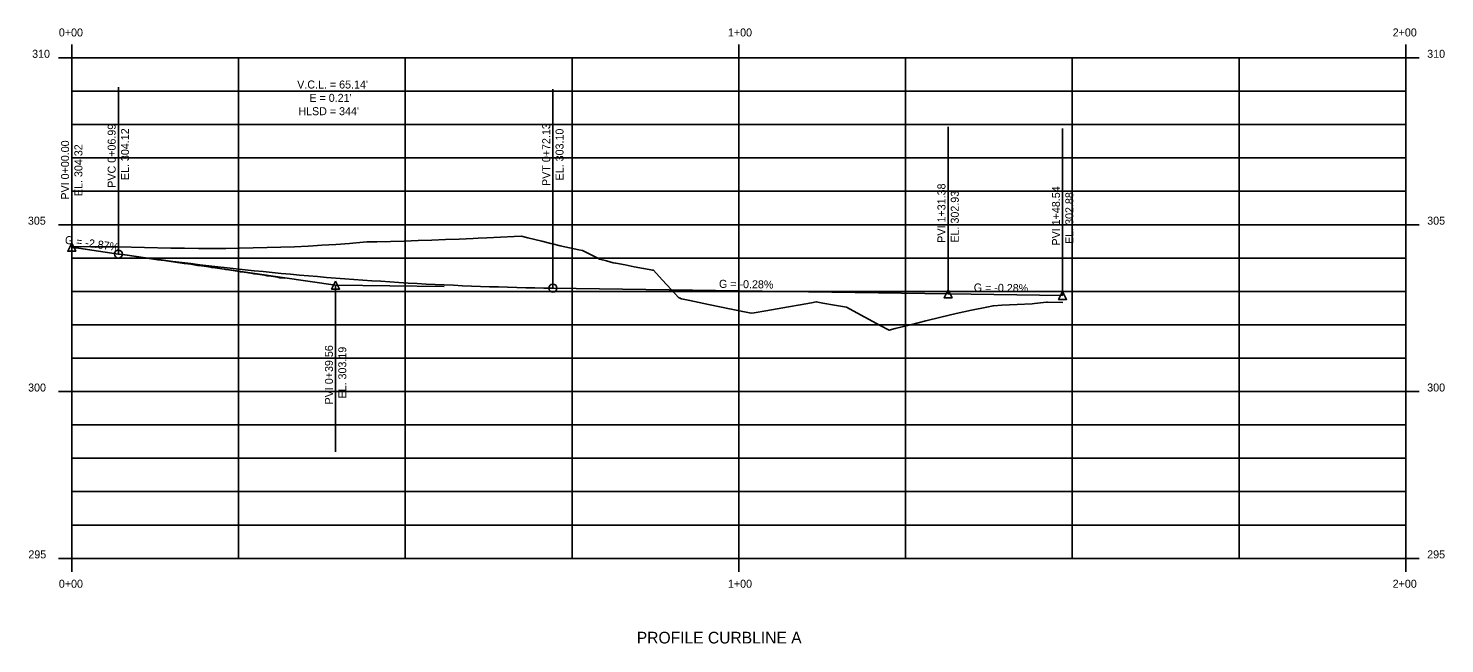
# Model space of a CAD drawing. Extents: x 916627 to 921213, y 329780 to 330157.
# Drawn here: x 919973.2 to 920185.5, y 329794.6 to 329886.8 of the extents above; entities that cross this region are included whole.
import ezdxf

# ---------------------------------------------------------------- set-up
doc = ezdxf.new("R2010")
doc.units = 0
for name, color, linetype in [('D_Roadway_Centerline', 7, 'Continuous'), ('D_Roadway_Centerline_Bearings', 7, 'Continuous'), ('D_Roadway_Centerline_CurveData', 7, 'Continuous'), ('D_Roadway_Centerline_Text', 7, 'Continuous'), ('D_Roadway_Edge_TW', 7, 'Continuous')]:
    doc.layers.add(name, color=color, linetype=linetype)

msp = doc.modelspace()

# ---------------------------------------------------------------- linework, layer by layer
at = {"layer": 'D_Roadway_Centerline'}
for p, q in [((919979.72, 329884.41), (919979.72, 329882.41)), ((920079.72, 329884.41), (920079.72, 329882.41)), ((920179.72, 329884.41), (920179.72, 329882.41)), ((919977.72, 329882.41), (919979.72, 329882.41)), ((919977.72, 329882.41), (919979.72, 329882.41)), ((919979.72, 329882.41), (920179.72, 329882.41)), ((919979.72, 329807.41), (919979.72, 329882.41)), ((920079.72, 329807.41), (920079.72, 329882.41)), ((920179.72, 329807.41), (920179.72, 329882.41)), ((920181.72, 329882.41), (920179.72, 329882.41)), ((920181.72, 329882.41), (920179.72, 329882.41)), ((919977.72, 329857.41), (919979.72, 329857.41)), ((919979.72, 329857.41), (920179.72, 329857.41)), ((920181.72, 329857.41), (920179.72, 329857.41)), ((919979.72, 329854.02), (919986.71, 329853.01)), ((920051.85, 329847.9), (920111.1, 329847.06)), ((920111.1, 329847.06), (920128.27, 329846.82)), ((919977.72, 329832.41), (919979.72, 329832.41)), ((919979.72, 329832.41), (920179.72, 329832.41)), ((920181.72, 329832.41), (920179.72, 329832.41)), ((919977.72, 329807.41), (919979.72, 329807.41)), ((919979.72, 329807.41), (920179.72, 329807.41)), ((919979.72, 329805.41), (919979.72, 329807.41)), ((920079.72, 329805.41), (920079.72, 329807.41)), ((920181.72, 329807.41), (920179.72, 329807.41)), ((920179.72, 329805.41), (920179.72, 329807.41))]:
    msp.add_line(p, q, dxfattribs=at)
msp.add_lwpolyline([(919986.71, 329853.01), (919988.07, 329852.82), (919989.43, 329852.63), (919990.79, 329852.45), (919992.14, 329852.27), (919993.5, 329852.09), (919994.86, 329851.91), (919996.21, 329851.74), (919997.57, 329851.58), (919998.93, 329851.41), (920000.29, 329851.26), (920001.64, 329851.1), (920003, 329850.95), (920004.36, 329850.8), (920005.71, 329850.65), (920007.07, 329850.51), (920008.43, 329850.38), (920009.79, 329850.24), (920011.14, 329850.11), (920012.5, 329849.98), (920013.86, 329849.86), (920015.21, 329849.74), (920016.57, 329849.63), (920017.93, 329849.51), (920020.64, 329849.3), (920022, 329849.2), (920023.36, 329849.1), (920024.71, 329849.01), (920026.07, 329848.92), (920027.43, 329848.83), (920028.78, 329848.75), (920030.14, 329848.67), (920031.5, 329848.59), (920032.86, 329848.52), (920034.21, 329848.45), (920035.57, 329848.39), (920036.93, 329848.33), (920038.28, 329848.27), (920039.64, 329848.22), (920041, 329848.17), (920042.36, 329848.12), (920043.71, 329848.08), (920045.07, 329848.04), (920046.43, 329848), (920047.78, 329847.97), (920049.14, 329847.94), (920050.5, 329847.92), (920051.85, 329847.9)], dxfattribs=at)
at = {"layer": 'D_Roadway_Centerline_Bearings'}
msp.add_lwpolyline([(919979.72, 329854.14), (919982.59, 329854.07), (919986.7, 329854.07), (919994.59, 329853.91), (919996.65, 329853.88), (919998.71, 329853.86), (920000.76, 329853.85), (920002.82, 329853.86), (920004.88, 329853.88), (920006.94, 329853.92), (920009, 329853.97), (920011.06, 329854.03), (920013.12, 329854.11), (920015.17, 329854.2), (920015.92, 329854.24), (920017.23, 329854.32), (920019.29, 329854.46), (920021.35, 329854.61), (920023.41, 329854.78), (920023.96, 329854.82), (920025.47, 329854.85), (920027.53, 329854.9), (920029.58, 329854.96), (920031.64, 329855.02), (920033.7, 329855.09), (920035.76, 329855.17), (920037.82, 329855.26), (920039.88, 329855.36), (920040.64, 329855.4), (920041.94, 329855.45), (920043.99, 329855.54), (920046.05, 329855.63), (920047.15, 329855.69), (920048.11, 329855.45), (920050.17, 329854.93), (920051.56, 329854.57), (920051.78, 329854.52), (920052.95, 329854.26), (920054.34, 329853.96), (920055.72, 329853.66), (920056.3, 329853.53), (920057.11, 329853.13), (920058.5, 329852.43), (920058.85, 329852.25), (920059.89, 329851.97), (920060.87, 329851.71), (920061.28, 329851.63), (920062.67, 329851.37), (920064.06, 329851.11), (920065.45, 329850.85), (920066.83, 329850.59), (920066.91, 329850.58), (920068.22, 329849.16), (920069.61, 329847.64), (920070.67, 329846.48), (920070.94, 329846.39), (920071, 329846.37), (920071.15, 329846.31), (920072.39, 329846.05), (920073.78, 329845.76), (920075.17, 329845.47), (920076.88, 329845.11), (920078.6, 329844.76), (920080.32, 329844.4), (920081.57, 329844.14), (920082.03, 329844.22), (920083.75, 329844.51), (920085.47, 329844.81), (920087.18, 329845.11), (920088.9, 329845.41), (920090.62, 329845.72), (920091.34, 329845.85), (920092.33, 329845.65), (920094.05, 329845.36), (920095.88, 329845.07), (920096.33, 329844.82), (920098.61, 329843.55), (920100.9, 329842.31), (920102.28, 329841.58), (920103.18, 329841.83), (920105.46, 329842.42), (920107.74, 329843), (920110.03, 329843.55), (920112.31, 329844.08), (920114.59, 329844.58), (920116.88, 329845.06), (920117.85, 329845.25), (920117.87, 329845.25), (920117.89, 329845.26), (920119.16, 329845.34), (920121.44, 329845.46), (920123.72, 329845.57), (920124.06, 329845.59), (920125.86, 329845.8), (920126.01, 329845.8), (920128.29, 329845.76)], dxfattribs=at)
at = {"layer": 'D_Roadway_Centerline_CurveData'}
for p, q in [((919979.72, 329854.02), (919979.72, 329879.02)), ((919986.71, 329853.01), (919986.71, 329878.01)), ((920051.85, 329847.9), (920051.85, 329877.72)), ((920051.85, 329847.9), (920051.85, 329872.9)), ((920111.1, 329847.06), (920111.1, 329872.06)), ((920128.27, 329846.82), (920128.27, 329871.82)), ((920003, 329850.69), (920019.28, 329848.36)), ((920019.28, 329848.36), (920035.57, 329848.13)), ((920019.28, 329848.36), (920019.28, 329823.36))]:
    msp.add_line(p, q, dxfattribs=at)
msp.add_lwpolyline([(919986.71, 329877.41), (920051.85, 329877.41)], dxfattribs=at)
for points in [[(919979.72, 329854.62), (919980.32, 329853.42), (919979.12, 329853.42)], [(920019.28, 329848.96), (920019.88, 329847.76), (920018.68, 329847.76)], [(920111.1, 329847.66), (920111.7, 329846.46), (920110.5, 329846.46)], [(920128.27, 329847.42), (920128.87, 329846.22), (920127.67, 329846.22)]]:
    msp.add_lwpolyline(points, close=True, dxfattribs=at)
for centre in [(919986.71, 329853.01), (920051.85, 329847.9)]:
    msp.add_circle(centre, 0.6, dxfattribs=at)
at = {"layer": 'D_Roadway_Centerline_Text'}
for p, q in [((920004.72, 329807.41), (920004.72, 329882.41)), ((920029.72, 329807.41), (920029.72, 329882.41)), ((920054.72, 329807.41), (920054.72, 329882.41)), ((920104.72, 329807.41), (920104.72, 329882.41)), ((920129.72, 329807.41), (920129.72, 329882.41)), ((920154.72, 329807.41), (920154.72, 329882.41)), ((919979.72, 329877.41), (920179.72, 329877.41)), ((919979.72, 329872.41), (920179.72, 329872.41)), ((919979.72, 329867.41), (920179.72, 329867.41)), ((919979.72, 329862.41), (920179.72, 329862.41)), ((919979.72, 329852.41), (920179.72, 329852.41)), ((919979.72, 329847.41), (920179.72, 329847.41)), ((919979.72, 329842.41), (920179.72, 329842.41)), ((919979.72, 329837.41), (920179.72, 329837.41)), ((919979.72, 329827.41), (920179.72, 329827.41)), ((919979.72, 329822.41), (920179.72, 329822.41)), ((919979.72, 329817.41), (920179.72, 329817.41)), ((919979.72, 329812.41), (920179.72, 329812.41))]:
    msp.add_line(p, q, dxfattribs=at)
at = {"layer": 'D_Roadway_Edge_TW'}
msp.add_lwpolyline([(919979.72, 329854.02), (919979.78, 329854.01), (919980.77, 329853.87), (919981.76, 329853.72), (919982.75, 329853.58), (919983.75, 329853.44), (919984.74, 329853.3), (919985.73, 329853.15), (919986.72, 329853.01), (919987.71, 329852.87), (919988.7, 329852.73), (919989.68, 329852.59), (919990.67, 329852.45), (919991.66, 329852.3), (919992.65, 329852.16), (919993.63, 329852.02), (919994.59, 329851.89), (919994.59, 329851.89), (919994.62, 329851.88), (919995.6, 329851.75), (919995.61, 329851.75), (919996.6, 329851.6), (919996.63, 329851.59), (919996.65, 329851.59), (919996.69, 329851.58), (919997.58, 329851.47), (919997.59, 329851.47), (919998.58, 329851.31), (919998.58, 329851.31), (919998.67, 329851.3), (919998.71, 329851.29), (919998.79, 329851.28), (919999.57, 329851.18), (919999.57, 329851.18), (920000.56, 329851.02), (920000.57, 329851.02), (920000.7, 329851), (920000.76, 329850.99), (920000.87, 329850.97), (920001.56, 329850.89), (920001.56, 329850.89), (920002.56, 329850.73), (920002.56, 329850.73), (920002.75, 329850.7), (920002.82, 329850.69), (920002.94, 329850.67), (920003.56, 329850.59), (920003.56, 329850.59), (920004.56, 329850.44), (920004.57, 329850.43), (920004.79, 329850.39), (920004.88, 329850.38), (920005.01, 329850.36), (920005.57, 329850.29), (920005.57, 329850.29), (920006.58, 329850.13), (920006.58, 329850.13), (920006.84, 329850.09), (920006.94, 329850.07), (920007.07, 329850.05), (920007.58, 329849.99), (920007.59, 329849.99), (920008.6, 329849.83), (920008.6, 329849.83), (920008.89, 329849.78), (920009, 329849.76), (920009.13, 329849.74), (920009.61, 329849.68), (920009.62, 329849.68), (920010.63, 329849.52), (920010.63, 329849.52), (920010.94, 329849.46), (920011.06, 329849.45), (920011.19, 329849.43), (920011.65, 329849.37), (920011.65, 329849.37)], dxfattribs=at)

# ---------------------------------------------------------------- texts
at = {"layer": 'D_Roadway_Centerline_CurveData'}
for s, height, p in [('0+00', 1.2, (919977.79, 329885.61)), ('1+00', 1.2, (920078.09, 329885.61)), ('2+00', 1.2, (920177.74, 329885.61)), ('310', 1.2, (919973.78, 329882.41)), ('310', 1.2, (919973.78, 329882.41)), ('310', 1.2, (920182.92, 329882.41)), ('310', 1.2, (920182.92, 329882.41)), ("V.C.L. = 65.14'", 1.2, (920013.52, 329877.81)), ("E = 0.21'", 1.2, (920015.35, 329875.81)), ("HLSD = 344'", 1.2, (920013.69, 329873.81)), ('305', 1.2, (919973.15, 329857.41)), ('305', 1.2, (920182.92, 329857.41)), ('300', 1.2, (919973.18, 329832.41)), ('300', 1.2, (920182.92, 329832.41)), ('295', 1.2, (919973.22, 329807.41)), ('295', 1.2, (920182.92, 329807.41)), ('0+00', 1.2, (919977.79, 329803.01)), ('1+00', 1.2, (920078.09, 329803.01)), ('2+00', 1.2, (920177.74, 329803.01)), ('PROFILE CURBLINE A', 1.75, (920064.43, 329794.66))]:
    msp.add_text(s, height=height, dxfattribs=at).set_placement(p)
for s, rotation, p in [('PVC 0+06.99', 90, (919986.31, 329862.94)), ('PVT 0+72.13', 90, (920051.45, 329863.2)), ('PVI 0+00.00', 90, (919979.32, 329861.16)), ('EL. 304.12', 90, (919988.31, 329864.08)), ('EL. 303.10', 90, (920053.45, 329864.04)), ('EL. 304.32', 90, (919981.32, 329861.69)), ('PVI 1+31.38', 90, (920110.7, 329854.7)), ('EL. 302.93', 90, (920112.7, 329854.72)), ('PVI 1+48.54', 90, (920127.87, 329854.28)), ('EL. 302.88', 90, (920129.87, 329854.52)), ('G = -2.87%', 351.8291, (919978.63, 329854.58)), ('G = -0.28%', 359.1877, (920076.74, 329847.95)), ('G = -0.28%', 359.1967, (920114.94, 329847.4)), ('PVI 0+39.56', 90, (920018.88, 329830.47)), ('EL. 303.19', 90, (920020.88, 329831.36))]:
    msp.add_text(s, height=1.2, rotation=rotation, dxfattribs=at).set_placement(p)

doc.saveas('drawing.dxf')
